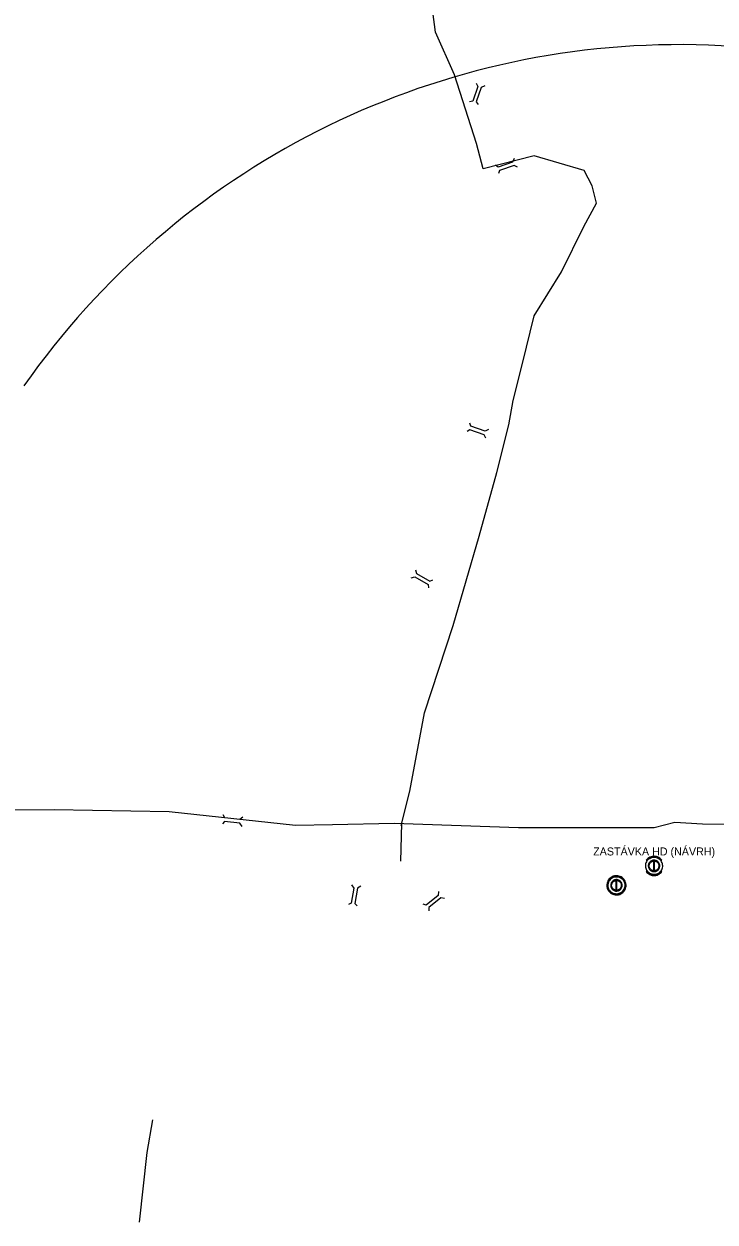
# Model space of a CAD drawing. Extents: x -520790 to -517278, y -1190021 to -1185077.
# Drawn here: x -519098 to -518752, y -1187365 to -1186766 of the extents above; entities that cross this region are included whole.
import ezdxf

# ---------------------------------------------------------------- set-up
doc = ezdxf.new("R2010")
doc.units = 0
for name, color, linetype in [('cyklostezka_n', 7, 'Continuous'), ('cyklostezka_s', 7, 'Continuous'), ('dostupnost_s', 7, 'Continuous'), ('most_s', 7, 'Continuous'), ('stezka_s', 7, 'Continuous'), ('zast_HD_n', 7, 'Continuous'), ('zast_HD_s', 7, 'Continuous')]:
    doc.layers.add(name, color=color, linetype=linetype)

msp = doc.modelspace()

# ---------------------------------------------------------------- linework, layer by layer
at = {"layer": 'cyklostezka_n'}
msp.add_lwpolyline([(-518909.06, -1187166.39), (-518904.87, -1187149.27), (-518897.53, -1187110.14), (-518883.2, -1187066.46), (-518870.1, -1187021.73), (-518861.36, -1186989.94), (-518855.42, -1186966.18), (-518853.15, -1186953.95), (-518848.44, -1186935.43), (-518842.67, -1186911.67), (-518829.04, -1186889.65), (-518817.86, -1186866.94), (-518811.57, -1186855.41), (-518813.67, -1186846.67), (-518817.7, -1186839.01), (-518842.67, -1186831.65), (-518868.09, -1186838.24), (-518871.57, -1186825.5), (-518882.5, -1186791.12), (-518891.94, -1186769.8), (-518895.08, -1186745.52)], dxfattribs=at)
at = {"layer": 'cyklostezka_s'}
msp.add_lwpolyline([(-519148.5, -1187158.48), (-519082.51, -1187158.33), (-519025.1, -1187159.41), (-518962.02, -1187166.21), (-518943.49, -1187165.91), (-518912.67, -1187165.14), (-518850.44, -1187167.37), (-518782.75, -1187167.37), (-518772.35, -1187164.69), (-518758.64, -1187165.51), (-518745.31, -1187165.71)], dxfattribs=at)
at = {"layer": 'dostupnost_s'}
msp.add_arc((-518769.97, -1187176.11), 400, 32.65634, 144.99756, dxfattribs=at)
at = {"layer": 'most_s'}
for points in [[(-518871.74, -1186795.33), (-518870.89, -1186797.07), (-518873.38, -1186804.29), (-518874.94, -1186804.77)], [(-518867.34, -1186796.66), (-518869.09, -1186797.5), (-518871.61, -1186804.71), (-518870.67, -1186806.05)], [(-518852.64, -1186833.08), (-518853.49, -1186834.83), (-518860.71, -1186837.32), (-518862.04, -1186836.39)], [(-518850.97, -1186837.36), (-518852.71, -1186836.51), (-518859.94, -1186838.98), (-518860.42, -1186840.54)], [(-518865.44, -1186968.45), (-518867.18, -1186969.3), (-518874.4, -1186966.81), (-518874.88, -1186965.25)], [(-518866.77, -1186972.85), (-518867.61, -1186971.1), (-518874.82, -1186968.58), (-518876.16, -1186969.52)], [(-518901.99, -1187038.56), (-518901.49, -1187040.43), (-518894.87, -1187044.25), (-518893.38, -1187043.58)], [(-518904.11, -1187042.64), (-518902.24, -1187042.12), (-518895.61, -1187045.91), (-518895.43, -1187047.53)], [(-518988.57, -1187166.8), (-518989.76, -1187165.27), (-518997.34, -1187164.34), (-518998.45, -1187165.54)], [(-518988.2, -1187162.21), (-518989.73, -1187163.42), (-518997.31, -1187162.52), (-518998.11, -1187161.09)], [(-518933.89, -1187196.06), (-518932.76, -1187197.65), (-518934.06, -1187205.17), (-518935.52, -1187205.89)], [(-518929.33, -1187196.67), (-518930.92, -1187197.78), (-518932.24, -1187205.3), (-518931.1, -1187206.47)], [(-518890.51, -1187199.37), (-518890.7, -1187201.3), (-518896.63, -1187206.12), (-518898.21, -1187205.69)], [(-518887.47, -1187202.82), (-518889.4, -1187202.61), (-518895.34, -1187207.41), (-518895.26, -1187209.04)]]:
    msp.add_lwpolyline(points, dxfattribs=at)
at = {"layer": 'stezka_s'}
for points in [[(-518909, -1187165.33), (-518909.41, -1187184.23), (-518909.41, -1187184.23)], [(-519039.9, -1187364.57), (-519036.07, -1187329.87), (-519033.21, -1187313.42)]]:
    msp.add_lwpolyline(points, dxfattribs=at)
at = {"layer": 'zast_HD_n'}
msp.add_line((-518782.53, -1187189.44), (-518782.53, -1187189.44), dxfattribs=at)
for points in [[(-518778.45, -1187186.58), (-518778.48, -1187186.03), (-518778.59, -1187185.5), (-518778.76, -1187184.98), (-518778.99, -1187184.48), (-518779.29, -1187184.02), (-518779.64, -1187183.6), (-518780.04, -1187183.23), (-518780.48, -1187182.91), (-518780.96, -1187182.65), (-518781.47, -1187182.46), (-518782, -1187182.33), (-518782.54, -1187182.26), (-518783.09, -1187182.27), (-518783.63, -1187182.34), (-518784.16, -1187182.48), (-518784.67, -1187182.69), (-518785.14, -1187182.96), (-518785.58, -1187183.29), (-518785.97, -1187183.67), (-518786.31, -1187184.1), (-518786.6, -1187184.56), (-518786.82, -1187185.06), (-518786.98, -1187185.59), (-518787.07, -1187186.12), (-518787.09, -1187186.67), (-518787.05, -1187187.22), (-518786.93, -1187187.75), (-518786.75, -1187188.27), (-518786.51, -1187188.75), (-518786.2, -1187189.21), (-518785.84, -1187189.62), (-518785.44, -1187189.98), (-518784.99, -1187190.29), (-518784.5, -1187190.54), (-518783.99, -1187190.73), (-518783.45, -1187190.85), (-518782.91, -1187190.9), (-518782.36, -1187190.88), (-518781.82, -1187190.8), (-518781.3, -1187190.64), (-518780.8, -1187190.42), (-518780.33, -1187190.14), (-518779.9, -1187189.81), (-518779.51, -1187189.42), (-518779.18, -1187188.98), (-518778.91, -1187188.51), (-518778.69, -1187188.01), (-518778.54, -1187187.48), (-518778.46, -1187186.94), (-518778.45, -1187186.58)], [(-518782.78, -1187181.78), (-518783.08, -1187181.79), (-518783.68, -1187181.86), (-518784.27, -1187182.01), (-518784.83, -1187182.24), (-518785.36, -1187182.53), (-518785.85, -1187182.89), (-518786.29, -1187183.31), (-518786.68, -1187183.78)], [(-518786.07, -1187183.78), (-518785.75, -1187183.44), (-518785.33, -1187183.09), (-518784.87, -1187182.8), (-518784.38, -1187182.56), (-518783.86, -1187182.39), (-518783.32, -1187182.29), (-518782.78, -1187182.26)], [(-518778.87, -1187183.78), (-518779.06, -1187183.54), (-518779.47, -1187183.1), (-518779.94, -1187182.71), (-518780.45, -1187182.38), (-518781, -1187182.12), (-518781.57, -1187181.93), (-518782.17, -1187181.81), (-518782.77, -1187181.78)], [(-518782.77, -1187182.26), (-518782.31, -1187182.28), (-518781.78, -1187182.37), (-518781.25, -1187182.53), (-518780.75, -1187182.76), (-518780.29, -1187183.04), (-518779.86, -1187183.39), (-518779.48, -1187183.78)], [(-518786.68, -1187183.78), (-518786.07, -1187183.78)], [(-518783.03, -1187183.72), (-518783.38, -1187183.77), (-518783.73, -1187183.87), (-518784.07, -1187184.01), (-518784.38, -1187184.19), (-518784.67, -1187184.42), (-518784.93, -1187184.67), (-518785.15, -1187184.96), (-518785.34, -1187185.27), (-518785.48, -1187185.61), (-518785.58, -1187185.95), (-518785.64, -1187186.31), (-518785.65, -1187186.68), (-518785.61, -1187187.04), (-518785.53, -1187187.39), (-518785.41, -1187187.73), (-518785.24, -1187188.06), (-518785.04, -1187188.36), (-518784.79, -1187188.63), (-518784.52, -1187188.87), (-518784.22, -1187189.07), (-518783.89, -1187189.23), (-518783.55, -1187189.35), (-518783.19, -1187189.42), (-518782.83, -1187189.45), (-518782.55, -1187189.45)], [(-518783.01, -1187188.98), (-518783.31, -1187188.93), (-518783.6, -1187188.85), (-518783.88, -1187188.73), (-518784.14, -1187188.57), (-518784.38, -1187188.38), (-518784.6, -1187188.16), (-518784.78, -1187187.92), (-518784.94, -1187187.66), (-518785.06, -1187187.38), (-518785.14, -1187187.08), (-518785.18, -1187186.78), (-518785.19, -1187186.48), (-518785.16, -1187186.17), (-518785.09, -1187185.88), (-518784.98, -1187185.59), (-518784.84, -1187185.32), (-518784.66, -1187185.07), (-518784.46, -1187184.84), (-518784.22, -1187184.65), (-518783.97, -1187184.48), (-518783.69, -1187184.34), (-518783.4, -1187184.25), (-518783.1, -1187184.19), (-518783.03, -1187184.18)], [(-518783.03, -1187184.18), (-518783.03, -1187183.71)], [(-518782.53, -1187189.44), (-518782.17, -1187189.39), (-518781.82, -1187189.29), (-518781.48, -1187189.15), (-518781.17, -1187188.96), (-518780.88, -1187188.74), (-518780.62, -1187188.49), (-518780.4, -1187188.2), (-518780.22, -1187187.89), (-518780.07, -1187187.55), (-518779.97, -1187187.2), (-518779.91, -1187186.84), (-518779.9, -1187186.48), (-518779.94, -1187186.12), (-518780.02, -1187185.76), (-518780.14, -1187185.42), (-518780.31, -1187185.1), (-518780.52, -1187184.8), (-518780.76, -1187184.53), (-518781.03, -1187184.29), (-518781.34, -1187184.09), (-518781.66, -1187183.93), (-518782, -1187183.81), (-518782.36, -1187183.73), (-518782.72, -1187183.7), (-518783.01, -1187183.71)], [(-518783.01, -1187183.71), (-518783.01, -1187188.98)], [(-518782.55, -1187189.45), (-518782.55, -1187184.17)], [(-518782.55, -1187184.17), (-518782.24, -1187184.22), (-518781.95, -1187184.31), (-518781.67, -1187184.43), (-518781.41, -1187184.59), (-518781.17, -1187184.78), (-518780.95, -1187184.99), (-518780.77, -1187185.24), (-518780.62, -1187185.5), (-518780.5, -1187185.78), (-518780.41, -1187186.08), (-518780.37, -1187186.38), (-518780.36, -1187186.68), (-518780.4, -1187186.99), (-518780.47, -1187187.28), (-518780.57, -1187187.57), (-518780.72, -1187187.84), (-518780.89, -1187188.09), (-518781.1, -1187188.31), (-518781.33, -1187188.51), (-518781.58, -1187188.68), (-518781.86, -1187188.81), (-518782.15, -1187188.91), (-518782.45, -1187188.97), (-518782.53, -1187188.98)], [(-518779.48, -1187183.78), (-518778.87, -1187183.78)], [(-518786.68, -1187189.38), (-518786.3, -1187189.85), (-518785.86, -1187190.26), (-518785.37, -1187190.62), (-518784.84, -1187190.92), (-518784.27, -1187191.14), (-518783.68, -1187191.3), (-518783.08, -1187191.37), (-518782.47, -1187191.37), (-518781.87, -1187191.3), (-518781.28, -1187191.14), (-518780.72, -1187190.92), (-518780.19, -1187190.63), (-518779.7, -1187190.27), (-518779.26, -1187189.85), (-518778.87, -1187189.38)], [(-518786.07, -1187189.38), (-518786.68, -1187189.38)], [(-518779.48, -1187189.38), (-518779.74, -1187189.66), (-518780.15, -1187190.02), (-518780.61, -1187190.32), (-518781.1, -1187190.56), (-518781.61, -1187190.74), (-518782.15, -1187190.86), (-518782.69, -1187190.9), (-518783.24, -1187190.88), (-518783.78, -1187190.78), (-518784.3, -1187190.62), (-518784.8, -1187190.4), (-518785.26, -1187190.11), (-518785.69, -1187189.77), (-518786.07, -1187189.38)], [(-518782.53, -1187188.98), (-518782.53, -1187189.44)], [(-518778.87, -1187189.38), (-518779.48, -1187189.38)]]:
    msp.add_lwpolyline(points, dxfattribs=at)
at = {"layer": 'zast_HD_s'}
msp.add_line((-518801.31, -1187199.16), (-518801.31, -1187199.16), dxfattribs=at)
for points in [[(-518801.56, -1187191.49), (-518801.96, -1187191.51), (-518802.56, -1187191.6), (-518803.15, -1187191.76), (-518803.7, -1187192), (-518804.23, -1187192.3), (-518804.71, -1187192.67), (-518805.14, -1187193.1), (-518805.52, -1187193.58), (-518805.83, -1187194.1), (-518806.07, -1187194.65), (-518806.24, -1187195.24), (-518806.34, -1187195.84), (-518806.36, -1187196.44), (-518806.3, -1187197.05), (-518806.17, -1187197.64), (-518805.96, -1187198.21), (-518805.69, -1187198.75), (-518805.34, -1187199.25), (-518804.94, -1187199.71), (-518804.48, -1187200.11), (-518803.98, -1187200.44), (-518803.43, -1187200.72), (-518802.86, -1187200.92), (-518802.27, -1187201.04), (-518801.66, -1187201.1), (-518801.06, -1187201.07), (-518800.46, -1187200.97), (-518799.88, -1187200.79), (-518799.32, -1187200.54), (-518798.8, -1187200.23), (-518798.33, -1187199.85), (-518797.91, -1187199.41), (-518797.54, -1187198.93), (-518797.24, -1187198.4), (-518797.01, -1187197.84), (-518796.85, -1187197.25), (-518796.77, -1187196.65), (-518796.76, -1187196.04), (-518796.83, -1187195.44), (-518796.98, -1187194.85), (-518797.2, -1187194.28), (-518797.48, -1187193.75), (-518797.84, -1187193.26), (-518798.25, -1187192.81), (-518798.72, -1187192.42), (-518799.23, -1187192.09), (-518799.78, -1187191.83), (-518800.35, -1187191.64), (-518800.95, -1187191.53), (-518801.56, -1187191.49)], [(-518801.56, -1187191.97), (-518801.2, -1187191.99), (-518800.66, -1187192.07), (-518800.13, -1187192.21), (-518799.63, -1187192.43), (-518799.15, -1187192.7), (-518798.72, -1187193.03), (-518798.33, -1187193.42), (-518797.99, -1187193.85), (-518797.71, -1187194.32), (-518797.5, -1187194.82), (-518797.34, -1187195.34), (-518797.26, -1187195.88), (-518797.24, -1187196.43), (-518797.29, -1187196.97), (-518797.41, -1187197.5), (-518797.59, -1187198.02), (-518797.84, -1187198.51), (-518798.15, -1187198.96), (-518798.52, -1187199.36), (-518798.93, -1187199.72), (-518799.38, -1187200.03), (-518799.87, -1187200.27), (-518800.39, -1187200.45), (-518800.92, -1187200.57), (-518801.47, -1187200.62), (-518802.01, -1187200.59), (-518802.55, -1187200.5), (-518803.07, -1187200.34), (-518803.57, -1187200.12), (-518804.04, -1187199.83), (-518804.47, -1187199.49), (-518804.85, -1187199.1), (-518805.17, -1187198.66), (-518805.44, -1187198.19), (-518805.65, -1187197.68), (-518805.8, -1187197.16), (-518805.87, -1187196.61), (-518805.88, -1187196.07), (-518805.81, -1187195.53), (-518805.68, -1187194.99), (-518805.49, -1187194.48), (-518805.23, -1187194), (-518804.91, -1187193.56), (-518804.54, -1187193.16), (-518804.12, -1187192.81), (-518803.66, -1187192.51), (-518803.16, -1187192.28), (-518802.64, -1187192.11), (-518802.11, -1187192.01), (-518801.56, -1187191.97)], [(-518797.24, -1187196.29), (-518797.27, -1187195.75), (-518797.37, -1187195.21), (-518797.54, -1187194.69), (-518797.78, -1187194.2), (-518798.07, -1187193.74), (-518798.42, -1187193.32), (-518798.82, -1187192.95), (-518799.27, -1187192.63), (-518799.75, -1187192.37), (-518800.26, -1187192.17), (-518800.79, -1187192.04), (-518801.33, -1187191.98), (-518801.88, -1187191.98), (-518802.42, -1187192.06), (-518802.95, -1187192.2), (-518803.45, -1187192.41), (-518803.93, -1187192.68), (-518804.37, -1187193), (-518804.76, -1187193.39), (-518805.1, -1187193.81), (-518805.38, -1187194.28), (-518805.61, -1187194.78), (-518805.77, -1187195.3), (-518805.86, -1187195.84), (-518805.88, -1187196.39), (-518805.83, -1187196.93), (-518805.72, -1187197.46), (-518805.54, -1187197.98), (-518805.29, -1187198.47), (-518804.99, -1187198.92), (-518804.63, -1187199.33), (-518804.22, -1187199.7), (-518803.77, -1187200.01), (-518803.29, -1187200.26), (-518802.77, -1187200.44), (-518802.24, -1187200.56), (-518801.69, -1187200.61), (-518801.15, -1187200.6), (-518800.61, -1187200.51), (-518800.08, -1187200.36), (-518799.58, -1187200.14), (-518799.11, -1187199.86), (-518798.68, -1187199.52), (-518798.3, -1187199.13), (-518797.97, -1187198.7), (-518797.69, -1187198.23), (-518797.48, -1187197.72), (-518797.33, -1187197.2), (-518797.25, -1187196.66), (-518797.24, -1187196.29)], [(-518801.81, -1187193.43), (-518802.17, -1187193.48), (-518802.52, -1187193.58), (-518802.85, -1187193.73), (-518803.16, -1187193.91), (-518803.45, -1187194.13), (-518803.71, -1187194.39), (-518803.93, -1187194.67), (-518804.12, -1187194.99), (-518804.26, -1187195.32), (-518804.37, -1187195.67), (-518804.42, -1187196.03), (-518804.43, -1187196.39), (-518804.4, -1187196.75), (-518804.32, -1187197.11), (-518804.19, -1187197.45), (-518804.02, -1187197.77), (-518803.82, -1187198.07), (-518803.58, -1187198.34), (-518803.3, -1187198.58), (-518803, -1187198.78), (-518802.67, -1187198.94), (-518802.33, -1187199.06), (-518801.97, -1187199.14), (-518801.61, -1187199.17), (-518801.33, -1187199.16)], [(-518801.79, -1187198.7), (-518802.09, -1187198.65), (-518802.38, -1187198.56), (-518802.66, -1187198.44), (-518802.93, -1187198.29), (-518803.17, -1187198.1), (-518803.38, -1187197.88), (-518803.57, -1187197.64), (-518803.72, -1187197.37), (-518803.84, -1187197.09), (-518803.92, -1187196.8), (-518803.96, -1187196.5), (-518803.97, -1187196.19), (-518803.94, -1187195.89), (-518803.87, -1187195.59), (-518803.76, -1187195.3), (-518803.62, -1187195.03), (-518803.44, -1187194.78), (-518803.24, -1187194.56), (-518803.01, -1187194.36), (-518802.75, -1187194.19), (-518802.48, -1187194.06), (-518802.19, -1187193.96), (-518801.89, -1187193.9), (-518801.81, -1187193.89)], [(-518801.81, -1187193.89), (-518801.81, -1187193.43)], [(-518801.31, -1187199.16), (-518800.95, -1187199.1), (-518800.6, -1187199), (-518800.27, -1187198.86), (-518799.95, -1187198.68), (-518799.66, -1187198.46), (-518799.41, -1187198.2), (-518799.18, -1187197.91), (-518799, -1187197.6), (-518798.85, -1187197.27), (-518798.75, -1187196.92), (-518798.7, -1187196.56), (-518798.69, -1187196.2), (-518798.72, -1187195.83), (-518798.8, -1187195.48), (-518798.93, -1187195.14), (-518799.09, -1187194.81), (-518799.3, -1187194.52), (-518799.54, -1187194.24), (-518799.82, -1187194.01), (-518800.12, -1187193.81), (-518800.44, -1187193.64), (-518800.79, -1187193.52), (-518801.14, -1187193.45), (-518801.51, -1187193.42), (-518801.79, -1187193.43)], [(-518801.79, -1187193.43), (-518801.79, -1187198.7)], [(-518801.56, -1187191.49), (-518801.56, -1187191.97)], [(-518801.56, -1187191.97), (-518801.56, -1187191.49)], [(-518801.33, -1187199.16), (-518801.33, -1187193.89)], [(-518801.33, -1187193.89), (-518801.03, -1187193.94), (-518800.73, -1187194.02), (-518800.45, -1187194.15), (-518800.19, -1187194.3), (-518799.95, -1187194.49), (-518799.74, -1187194.71), (-518799.55, -1187194.95), (-518799.4, -1187195.21), (-518799.28, -1187195.49), (-518799.2, -1187195.79), (-518799.15, -1187196.09), (-518799.15, -1187196.4), (-518799.18, -1187196.7), (-518799.25, -1187197), (-518799.36, -1187197.28), (-518799.5, -1187197.55), (-518799.67, -1187197.8), (-518799.88, -1187198.03), (-518800.11, -1187198.23), (-518800.37, -1187198.39), (-518800.64, -1187198.53), (-518800.93, -1187198.63), (-518801.23, -1187198.69), (-518801.31, -1187198.7)], [(-518801.31, -1187198.7), (-518801.31, -1187199.16)]]:
    msp.add_lwpolyline(points, dxfattribs=at)

# ---------------------------------------------------------------- texts
at = {"layer": 'zast_HD_n'}
msp.add_text('ZASTÁVKA HD (NÁVRH)', height=4, dxfattribs=at).set_placement((-518813.19, -1187181.36))

doc.saveas('drawing.dxf')
